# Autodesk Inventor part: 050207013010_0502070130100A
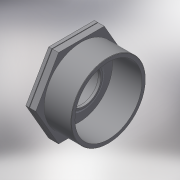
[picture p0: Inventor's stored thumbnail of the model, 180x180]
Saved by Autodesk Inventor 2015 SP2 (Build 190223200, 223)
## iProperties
Created: 2017-05
Part Number: 050207013010_0502070130100A
Material: Generic
Description: PLASSON REDUCING BUSHING 1.1/4"-1"
Document SubType Name: Modeling
Designer: KIM
Density: 1 g/cm^3
Appearance: Default
Author: KIM
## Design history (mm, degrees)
derived "050207.ipt"
feature "Solid1::050207.ipt"
tag "TaggingFeature1"
body "Solid1"
other parameters: "d1" = 41.91, "d2" = 46, "d5" = 21, "d8" = 0.37, "d12" = 0, "d15" = 37, "d19" = 0, "d30" = 9.25, "d31" = 4.625, "d33" = 30.291, "d34" = 37.719, "d36" = 2.3, "d37" = 36.3492, "d38" = 24.42, "d39" = 27.2619, "d40" = 2.1, "d41" = 0, "H_" = 37, "R_" = 41.91, "E_" = 46, "l_2" = 21, "Rp_" = 30.291
